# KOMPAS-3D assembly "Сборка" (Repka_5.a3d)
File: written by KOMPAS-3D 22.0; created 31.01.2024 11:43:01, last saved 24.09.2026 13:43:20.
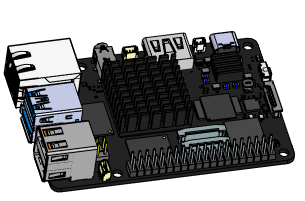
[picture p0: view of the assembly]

Document properties: Автор: User; Полное имя файла: ..\..\..\..\Pictures\Сборка.cdw

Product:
- Component [assembly]: REPKA-5-RK-1.0  | qty 1  | pos. 34  | Масса: 0.191575; Комментарий: REPKA-5-RK-1.0; source file: Repka_5_3D\Repka-5-RK-1.a3d
- Part/product: Сборка
    Масса: 0.191575
    Форматы листов документа: A3

Referenced files in C:\Users\User1\Downloads\1776423703614478_Repka-5-v1.0 (1)\Repka_5_3D\: Repka-5-RK-1.a3d
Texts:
  REPKA-5-RK-1.0 REPKA-5-RK-1.0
